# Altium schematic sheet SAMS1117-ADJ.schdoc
size 127 x 101 mm
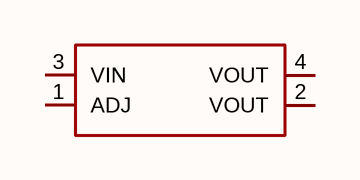
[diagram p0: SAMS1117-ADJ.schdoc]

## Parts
U?  sams1117-adj  [SOT-223-3_L6.4-W3.5-P2.30-LS7.0-BR]  (value not drawn)

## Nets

Not connected (* = marked no-connect by the designer): U? 1(ADJ) 2(VOUT) 3(VIN) 4(VOUT)

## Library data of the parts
U? = sams1117-adj: 输出极性:正极;工作电压:15V;输出电压:1.25V~12V;输出电流:1.2A;电源纹波抑制比(PSRR):-;输出类型:可调;; Manufacturer: JSMSEMI(杰盛微); AddInBom: yes; ModelId: 6654433eca7b4e7f8ee05e27058a22e4; ModelTransform: 251.968,275.59,0,90,0,0,-3.937,0,0; Output Configuration: 正极; Voltage - Supply: 15V; Output Current: 1.2A; Voltage Dropout: 1.3V@(800mA); Output Type: 可调; Number of Outputs: 1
